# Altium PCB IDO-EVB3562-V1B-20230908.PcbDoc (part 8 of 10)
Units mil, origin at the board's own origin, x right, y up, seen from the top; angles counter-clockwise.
Board outline 5314.96 x 3543.31 mil, 4 copper layers (TOP, L2-VCC, L3-GND, BOTTOM), stack 28.8 mil thick; 747 components, 560 nets, 2514 pads, 1964 vias.
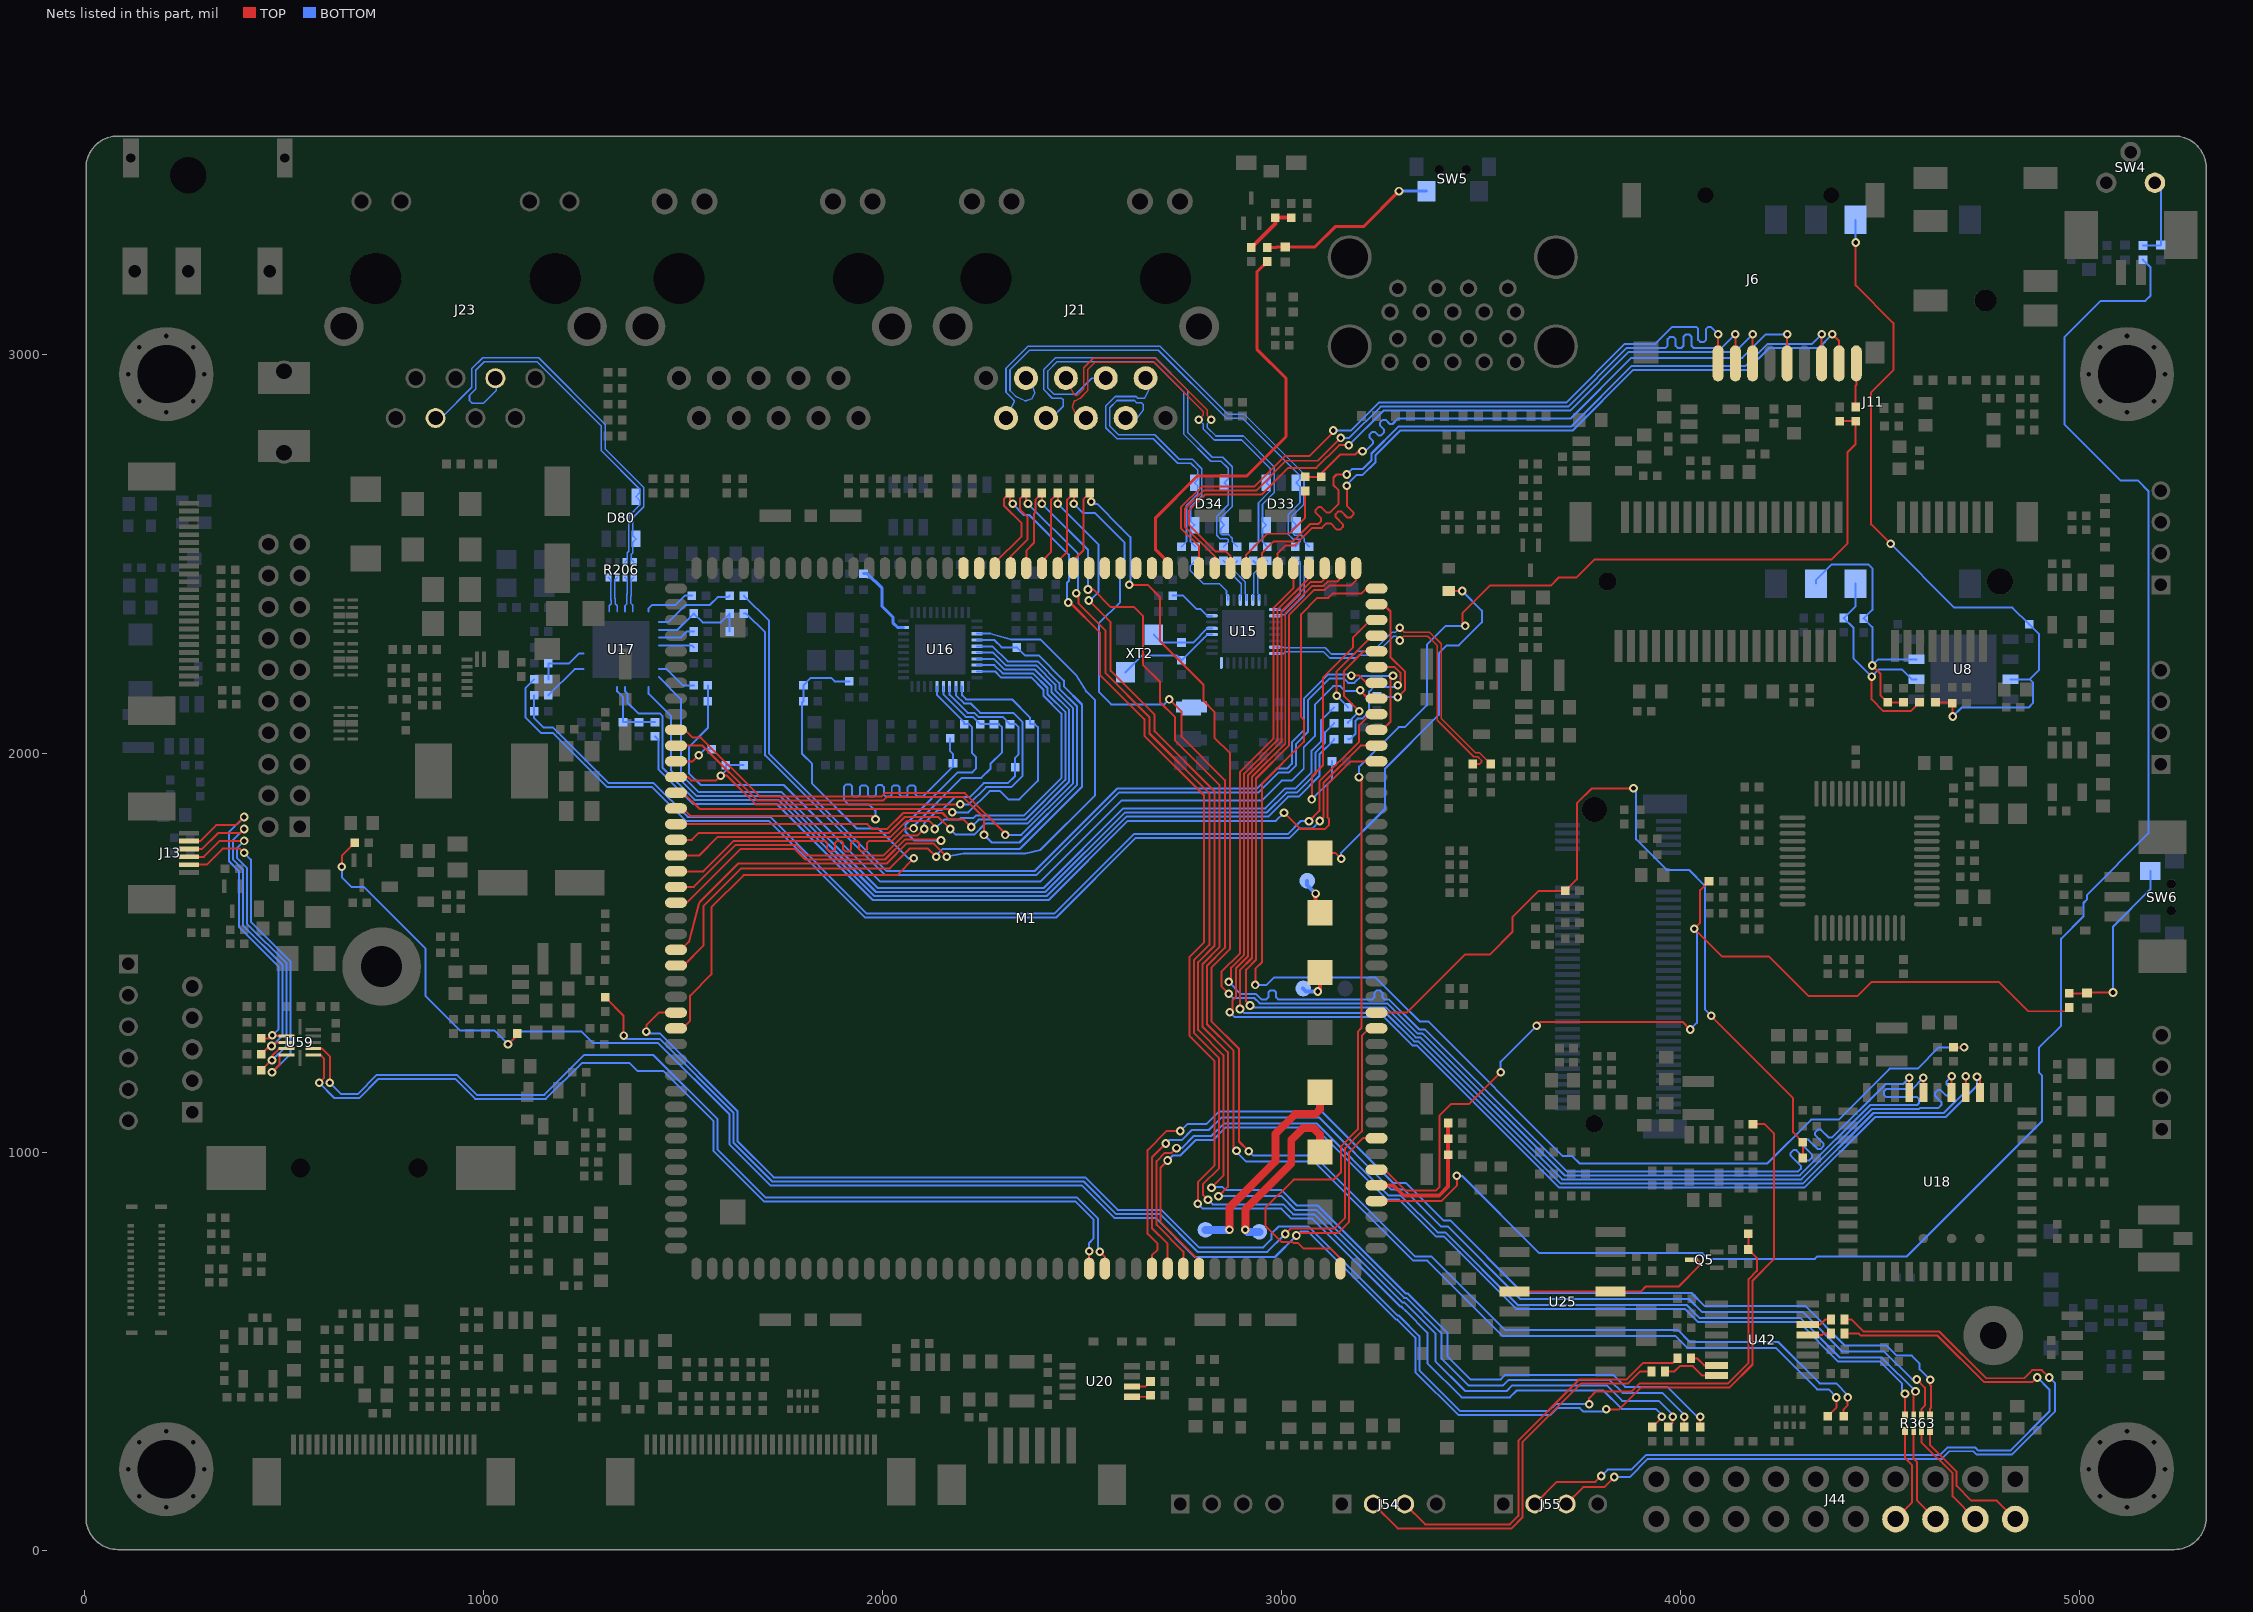
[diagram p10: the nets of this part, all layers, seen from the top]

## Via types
v1: diameter 21.65, hole 11.81, TOP to BOTTOM, 1964 vias

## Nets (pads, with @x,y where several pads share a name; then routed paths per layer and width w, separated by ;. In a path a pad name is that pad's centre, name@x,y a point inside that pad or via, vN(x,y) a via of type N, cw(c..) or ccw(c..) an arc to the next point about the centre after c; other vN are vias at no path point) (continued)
PHY2_MDI0-: R144.1 U15.2 | length 166.1
  BOTTOM w4: R144.1@2785,2482.28 2772,2469.28 2772,2458.14 2805.14,2425 2845,2425 2862.76,2407.24 2862.76,2398.24 2865.63,2395.37 U15.2@2865.63,2383.74
PHY2_MDI1+: R149.1 U15.4 | length 118.4
  BOTTOM w4: R149.1@2855,2482.28 2867.5,2469.78 2867.5,2457.5 2900,2425 2900,2399 2897.13,2396.13 U15.4@2897.13,2383.74
PHY2_MDI1-: R148.1 U15.5 | length 118.4
  BOTTOM w4: R148.1@2890,2482.28 2877.5,2469.78 2877.5,2461.64 2910,2429.14 2910,2399 2912.87,2396.13 U15.5@2912.87,2383.74
PHY2_MDI2+: R142.1 U15.6 | length 109.5
  BOTTOM w4: U15.6@2928.62,2383.74 2928.62,2396.62 2931.49,2399.49 2931.49,2450.64 2942.5,2461.64 2942.5,2469.78 R142.1@2930,2482.28
PHY2_MDI2-: R141.1 U15.7 | length 109.5
  BOTTOM w4: U15.7@2944.37,2383.74 2944.37,2396.63 2941.49,2399.51 2941.49,2446.49 2952.5,2457.5 2952.5,2469.78 R141.1@2965,2482.28
PHY2_MDI3+: R147.1 U15.9 | length 175.4
  BOTTOM w4: U15.9@2983.74,2360.12 2997.88,2360.12 3000.76,2357.24 3005.1,2357.24 3047.5,2399.64 3047.5,2478.5 3043.72,2482.28 R147.1@3035,2482.28
PHY2_MDI3-: R140.1 U15.10 | length 186.9
  BOTTOM w4: U15.10@2983.74,2344.37 2997.37,2344.37 3000.24,2347.24 3009.24,2347.24 3057.5,2395.5 3057.5,2469.78 R140.1@3070,2482.28
PHY2_MDI_0+: D34.4 J21.2 R145.2 | length 707.7
  BOTTOM w4: J21.2@2660,2940 2669,2913 2657.5,2890 2640.2,2890 2636.2,2894 2584,2894 2560,2870 2560,2816 2588,2788 2679,2788 2740.36,2726.64 2773.22,2726.64 2791,2708.86 2791,2686.55 D34.4@2782.6,2678.15 2791,2669.75 2791,2650.14 2762.5,2621.64 2762.5,2530.22 R145.2@2750,2517.72
PHY2_MDI_0-: D34.3 J21.3 R144.2 | length 707.7
  BOTTOM w4: J21.3@2610,2840 2621.6,2834.2 2639.31,2840.1 2654,2860.49 2654,2874.03 2650,2878.03 2638.03,2878.03 2632.05,2884 2588.14,2884 2570,2865.86 2570,2820.14 2592.14,2798 2683.14,2798 2744.51,2736.64 2777.36,2736.64 2801,2713 2801,2646 2772.5,2617.5 2772.5,2581.95 D34.3@2782.6,2571.85 2772.5,2561.75 2772.5,2530.22 R144.2@2785,2517.72
PHY2_MDI_1+: D34.6 J21.4 R149.2 | length 1088.6
  BOTTOM w4: J21.4@2560,2940 2525,2940 2485,2900 2430,2900 2415,2915 2415,2958 2438,2981 2679.86,2981 2756,2904.86 2756,2799 2823,2732 2848.86,2732 2867,2713.86 2867,2687.75 D34.6@2857.4,2678.15 2867,2668.55 2867,2622.41 2838,2593.41 2838,2546 2847,2537 2864.86,2537 2867.07,2534.79 2867.07,2529.79 R149.2@2855,2517.72
PHY2_MDI_1-: D34.1 J21.7 R148.2 | length 1088.8
  BOTTOM w4: J21.7@2410,2840 2424,2840 2453.29,2869.29 2453.29,2885.71 2449,2890 2425.86,2890 2405,2910.86 2405,2962.14 2433.86,2991 2684,2991 2766,2909 2766,2803.14 2827.14,2742 2853,2742 2877,2718 2877,2618.27 2848,2589.27 2848,2581.25 D34.1@2857.4,2571.85 2848,2562.45 2848,2550.14 2851.14,2547 2869,2547 2877.07,2538.93 2877.07,2530.65 R148.2@2890,2517.72
PHY2_MDI_2+: D33.4 J21.5 R142.2 | length 989.8
  TOP w4: J21.5@2510,2840 2486,2848 2476.4,2867.2 2481.57,2882.69 2495.84,2889.83 2515,2908.99 2515,2961.86 2533.14,2980 2680.86,2980 2804,2856.86 2804,2846.83 v1(2793.17,2836)
  BOTTOM w4: v1(2793.17,2836) 2804,2825.17 2804,2813 2832,2785 2901,2785 2972,2714 2972,2687.55 D33.4@2962.6,2678.15 2972,2668.75 2972,2657 2943,2628 2943,2530.72 R142.2@2930,2517.72
PHY2_MDI_2-: D33.3 J21.6 R141.2 | length 990.3
  TOP w4: J21.6@2460,2940 2480.98,2898.05 2486.34,2896.26 2489.92,2898.05 2505,2913.13 2505,2966 2529,2990 2685,2990 2814,2861 2814,2846.83 v1(2824.83,2836)
  BOTTOM w4: v1(2824.83,2836) 2814,2825.17 2814,2817.14 2836.14,2795 2905.14,2795 2982,2718.14 2982,2652.86 2953,2623.86 2953,2581.45 D33.3@2962.6,2571.85 2953,2562.25 2953,2529.72 R141.2@2965,2517.72
PHY2_MDI_3+: D33.6 J21.8 R147.2 | length 1281.2
  BOTTOM w4: J21.8@2360,2940 2372,2934 2382.2,2903.4 2374.6,2888.2 2358.4,2882.8 2333.71,2895.15 2320,2908.86 2320,2960.86 2369.14,3010 2691.87,3010 2861.87,2840 2902.38,2840 3047,2695.38 3047,2687.75 D33.6@3037.4,2678.15 3037.4,2677.6 3047,2668 3047,2628 3018,2599 3018,2547.86 3029.86,2536 3045.86,2536 3048,2533.86 3048,2530.72 R147.2@3035,2517.72
PHY2_MDI_3-: D33.1 J21.9 R140.2 | length 1269.3
  BOTTOM w4: J21.9@2310,2840 2330.98,2881.95 2330.02,2884.81 2329.78,2884.93 2310,2904.72 2310,2965 2365,3020 2696.01,3020 2866.01,2850 2906.52,2850 3057,2699.52 3057,2623.86 3028,2594.86 3028,2581.25 D33.1@3037.4,2571.85 3028,2562.45 3028,2552 3034,2546 3050,2546 3058,2538 3058,2529.72 R140.2@3070,2517.72
PHY2_REG_OUT: L32.1 R1064.1 U15.24
PHY2_XTALIN: C116.1 U15.28 XT2.3 | length 266
  BOTTOM w5: XT2.3@2609.57,2202.76 2651.81,2245 2737.72,2245 C116.1@2750,2232.72 2814.41,2297.13 U15.28@2826.26,2297.13
PHY2_XTALOUT: C115.1 U15.29 XT2.1 | length 168.8
  BOTTOM w5: XT2.1@2680.43,2297.24 2700.4,2277.28 C115.1@2750,2277.28 2779.15,2277.28 2814.74,2312.87 U15.29@2826.26,2312.87
PHY_INT: R195.1 U17.11 | length 94.2
  BOTTOM w5: U17.11@1439.5,2289.55 1494.55,2289.55 1510,2305 R195.1@1527.28,2305
PMIC_32KOUT_WIFI: M1.16 R243.1 R342.1 R391.1 | length 2146.4
  TOP w5: M1.16@3238.78,1349.61 3314.61,1349.61 3460,1495 3522.54,1495 3579.14,1551.6 3579.14,1589.17 3644.97,1655 R342.1@3712.28,1655 3741.08,1683.8 3741.08,1874.18 3778.91,1912 v1(3883,1912) ; v1(4077.7,1341.57) 4077.7,1340.38 4283,1135.08 4283,1049.28 R243.1@4307.28,1025 R391.1@4307.28,985
  BOTTOM w5: v1(3883,1912) 3889.5,1905.5 3889.5,1783.95 3965.95,1707.5 4022.17,1707.5 4061.67,1668 4061.67,1357.6 v1(4077.7,1341.57)
PMIC_EXT_EN: M1.8 R4.1 R9.1 R1171.1 | length 5602.8
  TOP w5: v1(645,1715) 645,1742.72 R4.1@677.28,1775 ; v1(1061.65,1270) 1085,1293.35 R9.1@1085,1297.28 ; v1(3038,790.67) 3044.33,797 3142,797 3170,825 3170,1000 3204.65,1034.65 M1.8@3238.78,1034.65 ; v1(3814.48,355) 3847.18,355 3902.48,410.3 4124.21,410.3 4181.35,467.44 4181.35,677.18 4235,730.83 4235,1046.67 4211.67,1070 R1171.1@4182.72,1070
  BOTTOM w5: v1(645,1715) 645,1689.08 669.08,1665 700,1665 855,1510 855,1391 941,1305 1026.65,1305 v1(1061.65,1270) 1093.65,1302 1246,1302 1274.33,1273.67 1437.42,1273.67 1616.91,1094.18 1616.91,1018.66 1719.25,916.33 2500.1,916.33 2581.43,835 2685,835 2783,737 2984.33,737 v1(3038,790.67) 3048.33,801 3066.71,801 3287.71,580 3291,580 3336.33,534.67 3336.33,448.53 3444.53,340.33 3673.94,340.33 3691.94,358.33 3748.67,358.33 3757.35,349.65 3809.12,349.65 v1(3814.48,355)
PMIC_PWRON: M1.4 R267.1 | length 4490.3
  TOP w5: M1.4@3238.78,877.16 3401.16,877.16 3440,916 v1(3440,940.5)
  BOTTOM w5: v1(3440,940.5) 3453.11,940.5 3646.94,746.67 4055.63,746.67 4070.09,732.21 4337.45,732.21 4343.46,738.22 4568.22,738.22 4906.67,1076.67 4906.67,1192.33 4899.35,1199.65 4899.35,1260.99 4955,1316.64 4955,1535 5011,1591 5011,1624.43 5020,1633.43 5020,1645 5173.88,1798.88 5173.88,2657.12 5147,2684 5103.22,2684 4963.5,2823.72 4963.5,3043.5 5054,3134 5166,3134 5179,3147 5179,3218.28 R267.1@5160,3237.28
PMIC_SLEEP_H: M1.15 R1083.1 | length 2746.1
  TOP w5: R1083.1@1305,1387.72 1351.6,1341.12 v1(1351.6,1292) ; v1(3010,794.67) 3024.33,809 3134,809 3160,835 3160,1010 3202,1052 3202,1292 3220.24,1310.24 M1.15@3238.78,1310.24
  BOTTOM w5: v1(1351.6,1292) 1359.92,1283.67 1441.56,1283.67 1626.91,1098.33 1626.91,1022.81 1723.39,926.33 2504.25,926.33 2585.57,845 2695,845 2790,750 2965.33,750 v1(3010,794.67)
PMIC_VDC: C302.2 M1.5 R17.1 R389.2 | length 359
  TOP w10: M1.5@3238.78,916.53 3281.47,916.53 3307,891 3396,891 3418.28,913.28 R17.1@3418.28,993 C302.2@3418.28,1033 R389.2@3418.28,1073
PWRON_KEY: D51.1 R267.2 SW4.1 | length 207.8
  BOTTOM w5: R267.2@5160,3272.72 5203.82,3272.72 D51.1@5205,3273.9 5205,3415 SW4.1@5190,3430
RECOVERY_KEY: D46.1 R264.2 SW5.4 | length 457.6
  TOP w8: R264.2@2965,3267.72 2987.72,3267.72 2988.9,3268.9 D46.1@3010,3268.9 3083.9,3268.9 3135,3320 3206.02,3320 v1(3295,3408.98)
  BOTTOM w8: v1(3295,3408.98) SW5.4@3364.05,3408.98
REFCLKN_100M_RJ45: R404.2 U15.16 | length 826.9
  TOP w4: v1(3297.17,2282.53) 3297.17,2284.01 3306.51,2293.36 3367.5,2293.36 3390.75,2270.11 3390.75,2082.8 3482.55,1991 3492.58,1991 3502,1981.58 3502,1977 3497.72,1972.72 R404.2@3480,1972.72
  BOTTOM w4: U15.16@2983.74,2249.88 3005.7,2249.88 3009.81,2254 3105.86,2254 3121.25,2238.6 3187.6,2238.6 3194,2245 3233.14,2245 3281.5,2293.36 3287.82,2293.36 3297.17,2284.01 v1(3297.17,2282.53)
REFCLKP_100M_RJ45: R403.2 U15.15 | length 826.6
  TOP w4: v1(3297.17,2314.18) 3307.99,2303.36 3371.64,2303.36 3400.75,2274.25 3400.75,2086.95 3486.7,2001 3496.72,2001 R403.2@3525,1972.72
  BOTTOM w4: U15.15@2983.74,2265.63 3005.7,2265.63 3007.32,2264 3110,2264 3125.4,2248.6 3183.46,2248.6 3189.86,2255 3229,2255 3277.36,2303.36 3286.34,2303.36 v1(3297.17,2314.18)
RESET_KEY: D50.1 R266.2 SW6.4 | length 454.1
  TOP w5: R266.2@4975,1397.72 5018.82,1397.72 D50.1@5020,1398.9 5021.1,1400 v1(5085,1400)
  BOTTOM w5: v1(5085,1400) 5085,1565 5178.48,1658.48 SW6.4@5178.48,1704.44
RESETN: M1.6 R36.1 R266.1 | length 2567.6
  TOP w5: M1.6@3238.78,955.91 3259.77,955.91 3312.18,903.5 3387.5,903.5 3397,913 3397,1092 3425,1120 3470,1120 v1(3550,1200) ; v1(3640,1316.67) 3649.33,1326 4006.08,1326 v1(4025,1307.08) ; R36.1@4072.28,1679 4050,1656.72 4050,1575 v1(4035,1560) 4105,1490 4223,1490 4322,1391 4444,1391 4479.93,1426.93 4798.07,1426.93 4872,1353 4965.72,1353 R266.1@4975,1362.28
  BOTTOM w5: v1(3550,1200) 3550,1226.67 v1(3640,1316.67) ; v1(4025,1307.08) 4041.67,1323.75 4041.67,1553.33 v1(4035,1560)
RGMII_CLK_M0: C130.2 M1.115 R170.1 R171.2 | length 1624.6
  TOP w5: M1.115@1482.87,1310.24 1499.24,1310.24 1517.93,1328.93 1517.93,1391.93 1571.29,1445.29 1571.29,1613.49 1652.15,1694.35 2036.86,1694.35 v1(2078.76,1736.25)
  BOTTOM w5: R170.1@1917.28,2180 1880.51,2180 1871.84,2188.66 1820.94,2188.66 R171.2@1802.28,2170 C130.2@1802.28,2130.01 1799.07,2126.81 1799.07,1997.87 1823.92,1973.02 1823.92,1923.52 1936.26,1811.18 1990.06,1811.18 2064.99,1736.25 v1(2078.76,1736.25)
RGMII_MDC_M0: M1.110 U16.13 | length 1871.8
  TOP w5: M1.110@1482.87,1507.09 1495.09,1507.09 1515.19,1527.19 1540.34,1623.2 1543.45,1628.08 1638.72,1723.35 2010.73,1723.35 2060.36,1772.98 2129.13,1772.98 v1(2161.65,1740.46)
  BOTTOM w5: v1(2161.65,1740.46) 2203.62,1748 2358.74,1748 2396.01,1757.17 2532.5,1893.66 2532.5,2133.46 2510.98,2154.98 2485.97,2195.32 2396.22,2285.07 2323.07,2285.07 2271,2299.37 U16.13@2237.52,2299.37
RGMII_MDIO_M0: M1.111 R191.1 U16.14 | length 1825.8
  TOP w5: M1.111@1482.87,1467.72 1501.72,1467.72 1552,1518 1552,1617 1646,1711 2019,1711 2069,1761 2114,1761 v1(2135,1740)
  BOTTOM w5: v1(2135,1740) 2135,1744 2151,1760 2345,1760 2500.5,1915.5 2500.5,2122.03 2454.97,2167.56 2454.97,2182.03 2392,2245 2357.28,2245 R191.1@2337.28,2265 2299,2265 2280.38,2283.62 U16.14@2237.52,2283.62
RGMII_RXCLK_M0: C143.2 M1.101 R192.2 | length 1238.4
  TOP w5: M1.101@1482.87,1861.42 1499.58,1861.42 1518.17,1842.83 1974.5,1842.83 v1(1982.83,1834.5)
  BOTTOM w5: v1(1982.83,1834.5) 1982.83,1855.17 1966.84,1871.16 1915.84,1871.16 1903.56,1883.44 1903.56,1915.67 1909.56,1921.67 1919.56,1921.67 1923.56,1917.67 1923.56,1896.16 1928.56,1891.16 1938.56,1891.16 1943.56,1896.16 1943.56,1914 1948.56,1919 1958.56,1919 1963.56,1914 1963.56,1896.16 1968.56,1891.16 1978.56,1891.16 1983.56,1896.16 1983.56,1914.76 1988.56,1919.76 1998.56,1919.76 2003.56,1914.76 2003.56,1896.16 2008.56,1891.16 2018.56,1891.16 2023.56,1896.16 2023.56,1914 2028.56,1919 2038.56,1919 2043.56,1914 2043.56,1896.16 2048.56,1891.16 2058.56,1891.16 2063.56,1896.16 2063.56,1914 2068.56,1919 2078.56,1919 2083.56,1914 2083.56,1896.16 2088.56,1891.16 2101.16,1891.16 2177.28,1967.28 C143.2@2177.28,1975.01 2177.28,1997.72 2170,2005 R192.2@2170,2037.28
RGMII_RXD0_M0: M1.105 R181.2 R182.1 U16.25 | length 1336.5
  TOP w5: M1.105@1482.87,1703.94 1551.43,1703.94 1627.49,1780 1856.86,1780 1861.86,1775 1861.86,1759 1866.86,1754 1876.86,1754 1881.86,1759 1881.86,1775 1886.86,1780 1896.86,1780 1901.86,1775 1901.86,1759 1906.86,1754 1916.86,1754 1921.86,1759 1921.86,1775 1926.86,1780 1936.86,1780 1941.86,1775 1941.86,1759 1946.86,1754 1956.86,1754 1961.86,1759 1961.86,1775 1966.86,1780 2024.95,1780 2056.26,1811.3 v1(2078.33,1811.3)
  BOTTOM w5: v1(2078.33,1811.3) 2078.33,1817.33 2199,1938 2248,1938 2271.11,1961.11 2271.11,1973.17 2300,2002.07 2300,2065 2292.28,2072.72 R182.1@2280,2072.72 R181.2@2245,2072.72 2226.65,2091.07 2208.93,2091.07 2152.87,2147.13 U16.25@2152.87,2167.48
RGMII_RXD1_M0: M1.106 R184.2 R185.1 U16.24 | length 1349.3
  TOP w5: M1.106@1482.87,1664.57 1527.57,1664.57 1633,1770 1783.95,1770 1810.61,1743.35 2002.44,1743.35 2052.07,1792.98 2087.98,1792.98 v1(2105,1810)
  BOTTOM w5: v1(2105,1810) 2105,1823.83 2138.17,1857 2149,1857 2182,1890 2219,1890 2253.72,1924.72 2314.72,1924.72 2332.72,1942.72 R185.1@2332.72,1965 2332.72,1988.35 2341.65,1997.28 2341.65,2065.35 2334.28,2072.72 R184.2@2320,2072.72 2301.65,2091.07 2240.79,2091.07 2230.79,2101.07 2213.93,2101.07 2168.62,2146.38 U16.24@2168.62,2167.48
RGMII_RXD2_M0: M1.99 R187.2 R188.1 U16.23 | length 1363.9
  TOP w5: M1.99@1482.87,1940.16 1512.46,1940.16 1520.62,1932 1583.57,1932 v1(1595,1943.43) 1610.49,1943.43 1682.25,1871.67 v1(2195,1871.67)
  BOTTOM w5: v1(1595,1943.43) 1607.72,1956.15 R187.2@1607.72,1970 R188.1@1652.28,1970 ; U16.23@2184.37,2167.48 2184.37,2145.63 2205,2125 2221.01,2125 2244.93,2101.07 2327.93,2101.07 2351.65,2077.35 2351.65,1943.77 2322.6,1914.72 2260.01,1914.72 2216.96,1871.67 v1(2195,1871.67)
RGMII_RXD3_M0: M1.100 R178.1 U16.22 | length 1367.6
  TOP w5: M1.100@1482.87,1900.79 1501.21,1900.79 1542,1860 2166.67,1860 v1(2175,1851.67)
  BOTTOM w5: v1(2175,1851.67) 2215.67,1851.67 2268.72,1904.72 2295.28,1904.72 2316,1884 2343.72,1884 2390,1930.28 2390,2065 2382.28,2072.72 R178.1@2370,2072.72 2370,2090 2325,2135 2210,2135 2200.12,2144.88 U16.22@2200.12,2167.48
RGMII_RXDV_M0: M1.107 R180.2 U16.26 | length 1357
  TOP w5: M1.107@1482.87,1625.2 1510.2,1625.2 1645,1760 1779.81,1760 1806.46,1733.35 2006.58,1733.35 2056.21,1782.98 2145.05,1782.98 v1(2147.02,1781.01)
  BOTTOM w5: U16.26@2137.13,2167.48 2137.13,2145.59 2205,2077.72 R180.2@2205,2072.72 2217.28,2072.72 2225,2065 2225,2000 2234.54,1990.46 2234.54,1961.05 2225.49,1952 2189,1952 2058,1821 2058,1803 2079.99,1781.01 v1(2147.02,1781.01)
RGMII_TXCLK_M0: M1.98 R177.1 | length 102
  TOP w5: M1.98@1482.87,1979.53 1524.53,1979.53 v1(1540,1995)
  BOTTOM w5: v1(1540,1995) 1555,2010 R177.1@1572.28,2010
RGMII_TXD0_M0: M1.102 U16.18 | length 1509.6
  TOP w5: M1.102@1482.87,1822.05 1962.3,1822.05 1974.35,1810 2012.52,1810 2052.52,1850 2150.75,1850 2167.41,1833.35 2204.43,1833.35 v1(2222.89,1814.88)
  BOTTOM w5: v1(2222.89,1814.88) 2241.38,1833.37 2358.8,1833.37 2458.5,1933.07 2458.5,2103.46 2413.97,2147.99 2413.97,2163.32 2377.29,2200 2301.43,2200 2280.8,2220.63 U16.18@2237.52,2220.63
RGMII_TXD1_M0: M1.103 U16.17 | length 1554.7
  TOP w5: M1.103@1482.87,1782.68 1522.68,1782.68 1540,1800 2016.66,1800 2056.66,1840 2140,1840 v1(2170,1810)
  BOTTOM w5: v1(2170,1810) 2184.08,1795.92 2229.85,1795.92 2257.3,1823.37 2362.94,1823.37 2468.5,1928.93 2468.5,2108.6 2423.97,2153.13 2423.97,2167.46 2381.43,2210 2305.57,2210 2279.19,2236.38 U16.17@2237.52,2236.38
RGMII_TXD2_M0: M1.96 U16.16 | length 1662.4
  TOP w5: M1.96@1482.87,2058.27 1504.73,2058.27 1524.2,2038.8 1545.2,2038.8 1692.17,1891.83 1998.29,1891.83 2006.46,1900 2206.74,1900 2308.16,1798.58 v1(2308.16,1795)
  BOTTOM w5: U16.16@2237.52,2252.13 2277.59,2252.13 2309.72,2220 2385.57,2220 2433.97,2171.61 2433.97,2157.28 2478.5,2112.74 2478.5,1924.79 2348.71,1795 v1(2308.16,1795)
RGMII_TXD3_M0: M1.97 U16.15 | length 1716.1
  TOP w5: M1.97@1482.87,2018.9 1549.17,2018.9 1686.24,1881.83 2002.43,1881.83 2010.6,1890 2202.59,1890 2254.85,1837.75 v1(2254.85,1795)
  BOTTOM w5: U16.15@2237.52,2267.87 2275.99,2267.87 2313.86,2230 2389.72,2230 2443.97,2175.75 2443.97,2161.42 2488.5,2116.89 2488.5,1920.64 2343.86,1776 2273.85,1776 v1(2254.85,1795)
RGMII_TXEN_M0: M1.104 U16.19 | length 1492
  TOP w5: M1.104@1482.87,1743.31 1540.31,1743.31 1587,1790 2020.81,1790 2060.81,1830 2118,1830 2131.65,1816.35 v1(2131.65,1810)
  BOTTOM w5: v1(2131.65,1810) 2155,1833.35 2191.35,1833.35 2196,1838 2229,1838 2234.37,1843.37 2354.66,1843.37 2448.5,1937.21 2448.5,2099.31 2403.97,2143.85 2403.97,2159.18 2373.14,2190 2297.28,2190 2282.4,2204.88 U16.19@2237.52,2204.88
RMII_CLK: C155.2 M1.36 R213.1 | length 2372.5
  TOP w5: v1(3198.05,2158.01) 3198.05,2156.44 3217.48,2137.01 M1.36@3238.78,2137.01
  BOTTOM w5: R213.1@1562.72,2170 C155.2@1562.72,2129.99 1562.72,2063 1515,2015.28 1515,1950 1544.89,1920.11 1752.38,1920.11 1994.56,1677.92 2395.92,1677.92 2599.8,1881.8 2951.78,1881.8 3000.91,1930.93 3026.77,1930.93 3056.35,1960.51 3056.35,2014.5 3085,2043.15 3085,2122.57 3130.18,2167.75 3147.96,2167.75 3159.61,2156.1 3196.14,2156.1 v1(3198.05,2158.01)
RMII_CLK_: R213.2 U17.15 | length 104.7
  BOTTOM w5: U17.15@1439.5,2210.75 1459.25,2210.75 1500,2170 R213.2@1527.28,2170
RMII_CLK_CTL: R216.1 U17.12 | length 89.8
  BOTTOM w5: U17.12@1439.5,2269.85 1522.43,2269.85 R216.1@1527.28,2265
RMII_CRS_DV: M1.35 R215.1 R1198.2 | length 2646.1
  TOP w5: v1(3069.55,1829.33) 3095.29,1855.07 3095.29,1929.37 3195,2029.08 3195,2070 3222.64,2097.64 M1.35@3238.78,2097.64
  BOTTOM w5: R215.1@1127.28,2145 R1198.2@1127.28,2105 1127.28,2087.72 1150.16,2064.84 1174.27,2064.84 1314.1,1925.02 1426.84,1925.02 1511.75,1840.11 1719.23,1840.11 1961.41,1597.92 2431.18,1597.92 2630.3,1797.04 3015.87,1797.04 3048.16,1829.33 v1(3069.55,1829.33)
RMII_CRS_DVALID: R215.2 U17.26 | length 115
  BOTTOM w5: R215.2@1162.72,2145 1228.47,2210.75 U17.26@1250.5,2210.75
RMII_MDC: M1.42 R203.1 | length 332.8
  TOP w5: M1.42@3238.78,2373.23 3255.77,2373.23 3273.84,2355.16 3273.84,2240.22 3310.49,2203.57 3310.49,2158.99 v1(3292.17,2140.66)
  BOTTOM w5: R203.1@3240,2142.72 3263.35,2142.72 3265.41,2140.66 v1(3292.17,2140.66)
RMII_MDIO: M1.41 R202.1 | length 642.9
  TOP w5: v1(3076.46,1883.99) 3076.46,1941.46 3104,1969 3104,2189.14 3180,2265.14 3180,2290 3223.86,2333.86 M1.41@3238.78,2333.86
  BOTTOM w5: v1(3076.46,1883.99) 3127.28,1934.81 R202.1@3127.28,1980
RMII_RST_: C340.2 R204.1 R208.2 U17.21 | length 173.9
  BOTTOM w5: U17.21@1335.15,2165.5 1335.15,2154.85 1350,2140 C340.2@1350,2077.72 R204.1@1390,2077.72 R208.2@1430,2077.72
RMII_RSTN: M1.32 R208.1 | length 2265.4
  TOP w5: v1(3006.97,1850.37) 3047.34,1810 3110,1810 3120,1820 3120,1835 3115.29,1839.71 3115.29,1921.09 3173.73,1979.53 M1.32@3238.78,1979.53
  BOTTOM w5: R208.1@1430,2042.28 1438.35,2033.93 1438.35,1959.93 1525.18,1873.11 1734.66,1873.11 1975.84,1631.92 2416.75,1631.92 2614.87,1830.04 2986.64,1830.04 v1(3006.97,1850.37)
RMII_RXD0: M1.37 R197.2 | length 2358
  TOP w5: v1(3175.72,2194.42) 3195.58,2194.42 3213.62,2176.38 M1.37@3238.78,2176.38
  BOTTOM w5: R197.2@1652.72,2395 1716.07,2331.65 1716.07,1998.84 2009.99,1704.92 2382.61,1704.92 2589.49,1911.8 2939.36,1911.8 2988.49,1960.93 3014.34,1960.93 3026.35,1972.94 3026.35,2026.93 3056.64,2057.22 3056.64,2136.64 3117.75,2197.75 3172.4,2197.75 v1(3175.72,2194.42)
RMII_RXD1: M1.34 R196.2 | length 2535
  TOP w5: M1.34@3238.78,2058.27 3253.27,2058.27 3273.84,2078.84 3273.84,2187.84 v1(3280,2194)
  BOTTOM w5: R196.2@1652.72,2350 1659,2350 1706.07,2302.93 1706.07,1994.7 2005.84,1694.92 2386.76,1694.92 2593.63,1901.8 2943.5,1901.8 2992.63,1950.93 3018.49,1950.93 3036.35,1968.79 3036.35,2022.79 3066.64,2053.07 3066.64,2132.49 3121.89,2187.75 3156.24,2187.75 3167.9,2176.1 3183.32,2176.1 3201.22,2194 v1(3280,2194)
RMII_RXER: M1.33 R210.1 | length 2674.9
  TOP w5: v1(3096.2,1830) 3105.29,1839.1 3105.29,1925.23 3198.96,2018.9 M1.33@3238.78,2018.9
  BOTTOM w5: R210.1@1127.28,2185 1105,2162.72 1105,2090 1145,2050 1174.97,2050 1309.95,1915.02 1422.69,1915.02 1507.61,1830.11 1715.09,1830.11 1957.27,1587.92 2435.33,1587.92 2634.44,1787.04 3020.01,1787.04 3043.97,1811 3077.2,1811 v1(3096.2,1830)
RMII_TXD0: M1.40 R199.1 | length 238.7
  TOP w5: v1(3139.07,2143.65) 3139.07,2205.07 3228.49,2294.49 M1.40@3238.78,2294.49
  BOTTOM w5: v1(3139.07,2143.65) R199.1@3167.72,2115
RMII_TXD0_: R199.2 U17.16 | length 2272.7
  BOTTOM w5: U17.16@1439.5,2191.05 1495,2135.55 1495,1947 1538.89,1903.11 1747.09,1903.11 1988.27,1661.92 2404.32,1661.92 2604.2,1861.8 2960.07,1861.8 3009.2,1910.93 3035.06,1910.93 3076.35,1952.22 3076.35,2006.22 3100,2029.87 3100,2082.72 R199.2@3132.28,2115
RMII_TXD1: M1.39 R198.1 | length 260
  TOP w5: v1(3195.16,2104.96) 3157.4,2142.72 3157.4,2206.39 3206.12,2255.12 M1.39@3238.78,2255.12
  BOTTOM w5: R198.1@3167.72,2075 3167.72,2077.52 v1(3195.16,2104.96)
RMII_TXD1_: R198.2 U17.17 | length 2243.3
  BOTTOM w5: U17.17@1413.95,2165.5 1413.95,2148.74 1470.44,2092.24 1470.44,1956.13 1533.46,1893.11 1742.95,1893.11 1984.13,1651.92 2408.47,1651.92 2608.34,1851.8 2964.21,1851.8 3013.34,1900.93 3039.2,1900.93 3086.35,1948.08 3086.35,2002.08 3110,2025.72 3110,2052.72 R198.2@3132.28,2075
RMII_TXEN: M1.38 R201.1 | length 328.4
  TOP w5: M1.38@3238.78,2215.75 3284.17,2215.75 3298.33,2201.59 3298.33,2176.16 v1(3292.17,2170)
  BOTTOM w5: R201.1@3167.72,2035 3172.72,2035 3186.07,2048.35 3186.07,2081.07 3191.63,2086.63 3202.75,2086.63 3220.3,2104.18 3220.3,2154.3 3232.1,2166.1 3288.26,2166.1 v1(3292.17,2170)
RMII_TXEN_: R201.2 U17.20 | length 2284.3
  BOTTOM w5: U17.20@1354.85,2165.5 1354.85,2155.09 1361,2148.94 1361,2127 1389,2099 1443,2099 1448.35,2093.65 1448.35,1964.08 1529.32,1883.11 1738.81,1883.11 1979.99,1641.92 2412.61,1641.92 2612.49,1841.8 2968.36,1841.8 3017.49,1890.93 3043.34,1890.93 3096.35,1943.94 3096.35,1997.93 3132.28,2033.86 R201.2@3132.28,2035
RN: R206.1 U17.6 | length 90.6
  BOTTOM w4: U17.6@1374.55,2354.5 1374.55,2370.45 1369.7,2375.3 1369.7,2394.7 1370.67,2395.67 1370.67,2434.49 R206.1@1376.5,2440.32
RP: R206.2 U17.5 | length 90.6
  BOTTOM w4: U17.5@1354.85,2354.5 1354.85,2369.85 1359.7,2374.7 1359.7,2398.84 1360.67,2399.81 1360.67,2434.49 R206.2@1354.84,2440.32
RS232_RX6: L42.1 U42.13 | length 59.6
  TOP w5: U42.13@4319.7,541.94 4355.94,541.94 4359,545 L42.1@4378.07,545
RS232_RX6_: J55.2 L42.2 | length 2029.7
  TOP w5: J55.2@3635.63,117.72 3690.91,173 3787.3,173 v1(3802.13,187.83) ; L42.2@4411.93,545 4448,545 4453,540 4645,540 4762,423 4883,423 v1(4895,435)
  BOTTOM w5: v1(3802.13,187.83) 3817.96,203.65 3877.43,203.65 3914.75,240.97 4651.82,240.97 4670.86,260 4739.08,260 4747.41,251.67 4827.49,251.67 4925.83,350.01 4925.83,404.17 v1(4895,435)
RS232_RX8: L41.1 U42.8 | length 144.7
  TOP w5: L41.1@3961.93,450 3985.7,450 3999,463.3 4031.71,463.3 4055.46,439.54 U42.8@4091.3,439.54
RS232_RX8_: J54.2 L41.2 | length 996.3
  TOP w5: J54.2@3230.63,117.72 3291.67,56.67 3577.32,56.67 3604.51,83.86 3604.51,272.69 3751.82,420 3869.75,420 3899.75,450 L41.2@3928.07,450
RS232_TX6: L43.1 U42.14 | length 63.5
  TOP w5: U42.14@4319.7,567.54 4350.54,567.54 4363,580 L43.1@4378.07,580
RS232_TX6_: J55.3 L43.2 | length 2009.9
  TOP w5: J55.3@3714.37,117.72 3756.65,160 3809.3,160 v1(3834.63,185.33) ; L43.2@4411.93,580 4430,580 4460,550 4650,550 4767,433 4862.08,433 4882.41,453.33 4906.67,453.33 v1(4925,435)
  BOTTOM w5: v1(3834.63,185.33) 3873.25,185.33 3918.89,230.97 4655.97,230.97 4675,250 4734.94,250 4743.27,241.67 4831.64,241.67 4940,350.04 4940,420 v1(4925,435)
RS232_TX8: L40.1 U42.7 | length 71.8
  TOP w5: L40.1@4026.93,483 4042.14,483 4060,465.14 U42.7@4091.3,465.14
RS232_TX8_: J54.3 L40.2 | length 987.9
  TOP w5: J54.3@3309.37,117.72 3360.41,66.67 3573.18,66.67 3594.51,88 3594.51,276.83 3747.68,430 3865.61,430 3907.28,471.67 3981.74,471.67 L40.2@3993.07,483
RSET0: R183.2 U16.39 | length 190.5
  BOTTOM w8: R183.2@1952.72,2450 1962.44,2450 1999.43,2413.02 1999.43,2367.7 2027,2340.13 2027,2326 2037.88,2315.12 U16.39@2052.48,2315.12
RSET2: R158.2 U15.31 | length 119.5
  BOTTOM w5: R158.2@2727.72,2395 2754.08,2395 2788.08,2361 2798.11,2361 2814.74,2344.37 U15.31@2826.26,2344.37
RXD0: R197.1 U17.9 | length 205.1
  BOTTOM w5: U17.9@1439.5,2328.95 1464.37,2328.95 1507.42,2372 1568,2372 1587,2391 1613.28,2391 R197.1@1617.28,2395
RXD1: R196.1 R211.1 R212.1 U17.10 | length 257.9
  BOTTOM w5: U17.10@1439.5,2309.25 1486.53,2309.25 R212.1@1527.28,2350 1549.28,2328 1595.28,2328 R196.1@1617.28,2350 R211.1@1617.28,2305
RXDV: R217.1 U17.8 | length 130.1
  BOTTOM w5: U17.8@1413.95,2354.5 1413.95,2362.95 1422,2371 1481,2371 1505,2395 R217.1@1522.28,2395
RXER/FXEN: R210.2 R220.1 U17.28 | length 138.2
  BOTTOM w5: R210.2@1162.72,2185 R220.1@1162.72,2225 1214.94,2225 1240.09,2250.15 U17.28@1250.5,2250.15
RXN: D80.4 J23.6 R206.8 | length 991.3
  BOTTOM w4: J23.6@880,2840 894,2840 971,2917 971,2964 998,2991 1138.4,2991 1305,2824.4 1305,2763 1402,2666 1402,2618 1374,2590 1374,2545.25 D80.4@1382.4,2536.85 1374,2528.45 1374,2501.86 1370.67,2498.53 1370.67,2485.51 R206.8@1376.5,2479.68
RXP: D80.3 J23.3 R206.7 | length 990.9
  BOTTOM w4: J23.3@1030,2940 1032,2938 1032,2909 1000,2877 972,2877 965,2884 965,2896.86 981,2912.86 981,2959.86 1002.14,2981 1134.26,2981 1295,2820.26 1295,2758.86 1392,2661.86 1392,2652.75 D80.3@1382.4,2643.15 1392,2633.55 1392,2622.14 1364,2594.14 1364,2506 1360.67,2502.67 1360.67,2485.51 R206.7@1354.84,2479.68
SARADC0_BOOT: M1.179 R1202.1 | length 948.8
  TOP w5: M1.179@3096.65,1750 3135,1750 v1(3150,1735) ; R1202.1@3420,2406.46 v1(3453.54,2406.46)
  BOTTOM w5: v1(3150,1735) 3150,1750 3260,1860 3260,1961 3395,2096 3395,2250 3415,2270 3445,2270 3503,2328 3503,2357 v1(3453.54,2406.46)
SARADC0_IN1_KEY/RECOVERY: M1.56 R264.1 | length 1030
  TOP w8: M1.56@2715.16,2463.78 2715.16,2479.84 2685,2510 2685,2590.07 2789.76,2694.83 2913.31,2694.83 3011.98,2793.49 3011.98,2939.66 2938.8,3012.84 2938.8,3206.07 R264.1@2965,3232.28
SARADC0_IN3: M1.57
SARADC0_IN4: M1.58
SARADC0_IN5: M1.59
SARADC0_IN6: M1.60
SARADC0_IN7: M1.61
SARADC1_IN0: C272.2 M1.62 R350.1 | length 3906.2
  TOP w5: M1.62@2478.94,2463.78 2478.94,2482.94 2504,2508 2504,2636.28 C272.2@2520,2652.28 2520,2636 2524,2632 v1(2524,2630) ; v1(2619.17,2421.84) 2665.16,2421.84 2696,2391 2696,2280 2805,2171 2805,2131 2832.5,2103.5 2832.5,2038.61 2871.65,1999.45 2871.65,1509.24 2824.8,1462.39 2824.8,1328.26 2894,1259.06 2894,1026.5 v1(2918.68,1001.82) ; R350.1@4410,337.72 4410,355 4420,365 v1(4420,385)
  BOTTOM w5: v1(2524,2630) 2527,2627 2529,2627 2531,2625 2538.36,2625 2598.02,2565.34 2621.68,2541.68 2621.68,2424.34 v1(2619.17,2421.84) ; v1(2918.68,1001.82) 2929.65,990.85 3082.72,990.85 3335,738.57 3376.25,738.57 3560.61,554.22 3993.51,554.22 4023.38,524.35 4245.27,524.35 4349.62,420 4391.11,420 4419.24,391.87 4419.24,385.76 v1(4420,385)
SARADC1_IN1: C273.2 M1.63 R349.1 | length 4052.7
  TOP w5: M1.63@2439.57,2463.78 2439.57,2481.57 2463.33,2505.33 2463.33,2635.61 C273.2@2480,2652.28 v1(2480,2625) ; v1(2719.32,2134.69) 2750,2104.01 2750,2041 2858.65,1932.35 2858.65,1511.8 2813.8,1466.95 2813.8,1320.88 2879.88,1254.8 2879.88,1011.09 v1(2887.88,1003.09) ; R349.1@4370,337.72 4391.59,359.31 v1(4391.59,384.63)
  BOTTOM w5: v1(2480,2625) 2503.33,2601.67 2533.4,2601.67 2606.68,2528.39 2606.68,2448 2595.85,2437.17 2595.85,2378.7 2542.5,2325.36 2542.5,2153.43 2573.66,2122.28 2706.91,2122.28 v1(2719.32,2134.69) ; v1(2887.88,1003.09) 2887.88,999.63 2911.66,975.85 3082.16,975.85 3330.44,727.57 3366.03,727.57 3554.39,539.22 3987.3,539.22 4017.16,509.35 4239.06,509.35 4343.41,405 4372.44,405 4391.59,385.86 v1(4391.59,384.63)
SARADC1_IN2: C274.2 M1.64 R348.1 | length 3721.1
  TOP w5: M1.64@2400.2,2463.78 2400.2,2481.2 2423.33,2504.33 2423.33,2635.61 C274.2@2440,2652.28 v1(2440,2625) ; v1(2517.23,2382.78) 2572,2328.01 2572,2206.42 2682.65,2095.77 2682.65,2054.68 2832.65,1904.68 2832.65,1516.91 2791.8,1476.06 2791.8,1306.11 2855,1242.91 2855,940.62 v1(2825.01,910.56) v1(2825.01,910.56) ; R348.1@4050,310.72 v1(4050,336.43)
  BOTTOM w5: v1(2440,2625) 2541.7,2523.3 2541.7,2403.53 2520.93,2382.77 v1(2517.23,2382.78) ; v1(2825.01,910.56) v1(2825.01,910.56) 2826.99,912.61 2852.34,912.61 2859.96,905 3000,905 3039,866 3091.86,866 3312.61,645.25 3317.69,645.25 3416.33,546.61 3416.33,487.88 3473.88,430.33 3550.33,430.33 3561.3,441.3 3831.88,441.3 3861.83,411.35 3968.07,411.35 4042.99,336.43 v1(4050,336.43)
SARADC1_IN3: C275.2 M1.65 R347.1 | length 3721
  TOP w5: M1.65@2360.83,2463.78 2360.83,2507.83 2380.2,2527.2 2380.2,2600.2 2383.33,2603.33 2383.33,2635.61 C275.2@2400,2652.28 v1(2400,2625) ; v1(2515.57,2410.39) 2528.61,2410.39 2573,2366 2631,2366 2653,2344 2653,2222 2695.99,2179.01 2695.99,2128.01 2734,2090 2734,2031.62 2845.65,1919.96 2845.65,1514.36 2802.8,1471.5 2802.8,1313.49 2866,1250.29 2866,912.61 v1(2842.68,889.29) ; R347.1@4010,310.72 v1(4010,336.43)
  BOTTOM w5: v1(2400,2625) 2515.57,2509.43 v1(2515.57,2410.39) ; v1(2842.68,889.29) 2843.39,890 2999.44,890 3034.44,855 3087.3,855 3308.05,634.25 3313.13,634.25 3397.33,550.05 3397.33,549.67 3401.33,545.67 3401.33,482.67 3469,415 3556,415 3569.3,428.3 3823.67,428.3 3855.62,396.35 3954.78,396.35 4010,341.13 v1(4010,336.43)
SARADC1_IN4: C276.2 M1.66 R346.1 | length 3727
  TOP w5: M1.66@2321.46,2463.78 2321.46,2493.46 2364,2536 2364,2591 2345,2610 2345,2637.28 C276.2@2360,2652.28 2360,2630.6 v1(2365,2625.6) ; v1(2485.83,2401.01) 2492,2394.84 2492,2375.02 2559,2308.02 2559,2201.04 2669.65,2090.38 2669.65,2049.29 2819.65,1899.29 2819.65,1519.65 2781,1481 2781,1480.82 2780.8,1480.62 2780.8,1298.72 2844,1235.52 2844,959.71 2803.68,919.39 2803.68,893.26 v1(2816.47,880.48) ; R346.1@3970,310.72 3981.1,321.82 v1(3981.1,336.42)
  BOTTOM w5: v1(2365,2625.6) 2490.83,2499.78 2490.83,2406.01 v1(2485.83,2401.01) ; v1(2816.47,880.48) 2827.94,869 2995.77,869 3004.88,869 3029.89,844 3082.74,844 3303.5,623.25 3308.58,623.25 3386.33,545.5 3386.33,475.67 3461,401 3565,401 3579.3,415.3 3815.45,415.3 3854.4,376.35 3946.5,376.35 3981.1,341.75 v1(3981.1,336.42)
SARADC1_IN5: C277.2 M1.67 R345.1 | length 3778.7
  TOP w5: M1.67@2282.09,2463.78 2282.09,2477.09 2349,2544 2349,2576 2305,2620 2305,2637.28 C277.2@2320,2652.28 2320,2631.67 v1(2326.67,2625) ; v1(2466.11,2377.61) 2470.38,2377.61 2546,2302 2546,2195.65 2656.65,2085 2656.65,2043.91 2806.65,1893.91 2806.65,1525.65 2769.8,1488.8 2769.8,1291.33 2775.61,1285.52 2833,1228.14 2833,967.1 2790.74,924.84 v1(2790.74,870.32) ; R345.1@3930,310.72 3953.44,334.16 v1(3953.44,336.42)
  BOTTOM w5: v1(2326.67,2625) 2354.67,2597 2368,2597 2467.5,2497.5 2467.5,2431.5 2462.5,2426.5 2462.5,2381.22 v1(2466.11,2377.61) ; v1(2790.74,870.32) 2803.07,858 3000.33,858 3018.89,839.44 3025.33,833 3078.19,833 3298.94,612.25 3301.18,612.25 3303.43,610 3311.77,601.66 3366.33,547.1 3366.33,470.67 3452,385 3573,385 3590.3,402.3 3807.24,402.3 3853.19,356.35 3938.21,356.35 3953.44,341.12 v1(3953.44,336.42)
SARADC1_IN6: M1.68
SARADC1_IN7: M1.69
SD_CD: J6.9 R28.2 | length 110
  TOP w5: R28.2@4440,2867.72 4440,2922 4441.46,2923.46 J6.9@4441.46,2977.13
SD_CLK: C279.2 J6.5 R25.2 | length 1504.9
  TOP w5: R25.2@3060,2692.72 C279.2@3100,2692.72 3100,2701 3147.61,2748.61 3185.47,2748.61 3193.62,2756.77 v1(3203.51,2756.77) ; J6.5@4268.23,2977.13 v1(4268.23,3050)
  BOTTOM w5: v1(3203.51,2756.77) 3210.49,2756.77 3229.39,2775.66 3229.39,2782.73 3220.59,2791.52 3220.59,2798.59 3227.67,2805.67 3234.74,2805.67 3243.53,2796.88 3250.6,2796.88 3257.67,2803.95 3257.67,2811.02 3247.24,2821.45 3247.24,2828.52 3254.31,2835.59 3261.38,2835.59 3271.82,2825.16 3278.89,2825.16 3292.48,2838.76 3725.1,2838.76 3877.25,2990.91 4155.91,2990.91 4215,3050 v1(4268.23,3050)
SDMMC0_CLK: M1.51 R25.1 | length 287
  TOP w5: M1.51@2912.01,2463.78 2912.01,2497.01 2965,2550 3020,2550 3060,2590 R25.1@3060,2657.28
SDMMC0_CMD: J6.3 M1.52 | length 1871.7
  TOP w5: M1.52@2872.64,2463.78 2872.64,2494.36 2861,2506 2834.6,2506 2768.55,2572.05 2768.55,2607.86 2809.02,2648.33 2951.33,2648.33 3018,2715 3087.91,2715 3144.85,2771.94 v1(3169.44,2771.94) ; J6.3@4181.61,2977.13 v1(4181.61,3050)
  BOTTOM w5: v1(3169.44,2771.94) 3256.26,2858.76 3723.88,2858.76 3871.04,3005.91 4137.52,3005.91 v1(4181.61,3050)
SDMMC0_D0: J6.7 M1.50 | length 1856.1
  TOP w5: M1.50@2951.38,2463.78 2951.38,2501.38 2980,2530 3028.28,2530 3073.28,2575 3093.32,2575 3099.99,2581.68 3099.99,2588.75 3085.91,2602.83 3085.91,2609.91 3092.98,2616.98 3100.05,2616.98 3114.14,2602.89 3121.21,2602.89 3144,2625.68 3144,2659 3131,2672 3131,2691 3138.51,2698.51 v1(3164.36,2698.51) ; J6.7@4354.84,2977.13 v1(4354.84,3050)
  BOTTOM w5: v1(3164.36,2698.51) 3178.39,2712.54 3204.82,2712.54 3226.17,2733.89 3226.17,2751.23 3293.7,2818.76 3726.31,2818.76 3878.47,2970.91 4164.2,2970.91 4218.5,3025.21 4330.05,3025.21 v1(4354.84,3050)
SDMMC0_D1: J6.8 M1.49 | length 1882.4
  TOP w5: M1.49@2990.75,2463.78 2990.75,2500.75 3010,2520 3032.43,2520 3077.43,2565 3102,2565 3113,2576 3123.84,2576 3139.38,2560.45 3147.45,2560.45 3154.52,2567.53 3154.52,2573.6 3136.1,2592.02 3136.1,2599.09 3143.17,2606.17 3150.24,2606.17 3165.67,2590.74 3173.74,2590.74 3180.81,2597.81 3180.81,2603.88 3164.38,2620.31 3164.38,2627.38 v1(3164.39,2670.47) ; v1(4381.49,3050) 4398.15,3033.34 J6.8@4398.15,2977.13
  BOTTOM w5: v1(3164.39,2670.47) 3164.39,2672.62 3189.56,2697.79 3204.21,2697.79 3236.17,2729.75 3236.17,2747.09 3297.84,2808.76 3730.45,2808.76 3882.61,2960.91 4168.34,2960.91 4222.64,3015.21 4346.7,3015.21 v1(4381.49,3050)
SDMMC0_D2: J6.1 M1.54 | length 1851.7
  TOP w5: M1.54@2793.9,2463.78 2793.9,2518.42 2748.55,2563.76 2748.55,2616.14 2800.73,2668.33 2932.76,2668.33 3008.93,2744.5 3070.5,2744.5 3130.07,2804.07 v1(3130.07,2808.99) ; J6.1@4095,2977.13 v1(4095,3050)
  BOTTOM w5: v1(3130.07,2808.99) 3174.99,2808.99 3244.76,2878.76 3714.12,2878.76 3861.28,3025.91 3938.02,3025.91 3980.61,3068.5 4040.02,3068.5 4045.02,3063.5 4045.02,3036 4050.02,3031 4060.02,3031 4065.02,3036 4065.02,3063.5 4070.02,3068.5 4076.5,3068.5 v1(4095,3050)
SDMMC0_D3: J6.2 M1.53 | length 1910.1
  TOP w5: M1.53@2833.27,2463.78 2833.27,2493.19 2758.55,2567.91 2758.55,2612 2804.88,2658.33 2936.9,2658.33 3011.57,2733 3091.77,2733 v1(3149.04,2790.27) ; J6.2@4138.31,2977.13 v1(4138.31,3050)
  BOTTOM w5: v1(3149.04,2790.27) 3170.41,2790.27 3248.9,2868.76 3718.88,2868.76 3866.04,3015.91 3963.36,3015.91 3968.36,3020.91 3968.36,3038 3973.36,3043 3983.36,3043 3988.36,3038 3988.36,3020.91 3993.36,3015.91 4003.36,3015.91 4008.36,3020.91 4008.36,3044 4013.36,3049 4023.36,3049 4028.36,3044 4028.36,3020.91 4033.36,3015.91 4104.23,3015.91 v1(4138.31,3050)
SDMMC0_DET_L: M1.171 R28.1 R431.2 | length 3489.2
  TOP w5: M1.171@3148.23,707.87 3148.23,734.27 3124.5,758 3056,758 3041.65,772.35 3030.41,772.35 3027.75,775 3000,775 2960,815 2960,860 3031,931 3131,931 3150,950 3150,1015 3192,1057 3192,1302 3201,1311 3201,1934 v1(3195,1940) ; v1(3461,2319) 3454,2326 3454,2351 3523,2420 3675,2420 3695,2440 3740,2440 3785,2485 4379,2485 4420,2526 4420,2755 4440,2775 R28.1@4440,2832.28 R431.2@4400,2832.28
  BOTTOM w5: v1(3195,1940) 3195,1966 3294,2065 3310,2065 3365,2120 3365,2272 3412,2319 v1(3461,2319)
SDMMC1_CLK: M1.43 R227.1 | length 3323
  TOP w5: v1(2935,1419.05) 2935,1459.44 2951.65,1476.1 2951.65,1923.16 3056.64,2028.14 3056.64,2083.36 3050,2090 3050,2348.6 3090.64,2389.24 3117.81,2389.24 3128.57,2400 3200,2400 3212.6,2412.6 M1.43@3238.78,2412.6 ; R227.1@4685,1262.72 v1(4711.68,1262.72)
  BOTTOM w5: v1(2935,1419.05) 2935.71,1418.35 2962.59,1418.35 2981.43,1437.18 3236.81,1437.18 3295.52,1378.47 3346.49,1327.5 3368.17,1327.5 3705.67,990 3729.23,990 3747.83,971.4 4218.32,971.4 4328.26,1081.34 4397.34,1081.34 4525.33,1209.33 4595.33,1209.33 4648.72,1262.72 v1(4711.68,1262.72)
SDMMC1_CMD: M1.44 U18.16 | length 3438.5
  TOP w5: v1(2921.67,1367.4) 2911.67,1377.39 2911.67,1457.33 2936.65,1482.31 2936.65,1936.44 3019.98,2019.77 3019.98,2346.87 3082.35,2409.24 3109.53,2409.24 3120.29,2420 3174,2420 3187.6,2433.6 M1.44@3187.6,2463.78 ; U18.16@4680.43,1149.41 v1(4680.43,1190)
  BOTTOM w5: v1(2921.67,1367.4) 2926.25,1362.82 3261.68,1362.82 3336.99,1287.5 3347.89,1287.5 3703.99,931.4 4303.97,931.4 4480.51,1107.94 4598.37,1107.94 4601.34,1110.91 4647.91,1110.91 4654.98,1117.98 4654.98,1125.05 4638.77,1141.27 4638.77,1148.34 4645.84,1155.41 4652.91,1155.41 4667.12,1141.19 4674.19,1141.19 4681.27,1148.27 4681.27,1155.34 4667.05,1169.55 4667.05,1176.62 v1(4680.43,1190)
SDMMC1_D0: M1.48 U18.18 | length 3404.6
  TOP w5: v1(2868.13,1397) 2849.8,1415.33 2849.8,1452.03 2896.65,1498.89 2896.65,1953.02 2979.98,2036.34 2979.98,2363.44 3030.12,2413.57 M1.48@3030.12,2463.78 ; U18.18@4609.57,1149.41 v1(4609.57,1186)
  BOTTOM w5: v1(2868.13,1397) 2879.4,1385.73 2932.84,1385.73 2945.76,1372.82 3265.82,1372.82 3341.14,1297.5 3353.89,1297.5 3709.99,941.4 4299.83,941.4 4476.37,1117.94 4594.23,1117.94 4599.23,1122.94 4599.23,1132.94 4594.23,1137.94 4516.37,1137.94 4511.37,1142.94 4511.37,1152.94 4516.37,1157.94 4581.51,1157.94 v1(4609.57,1186)
SDMMC1_D1: M1.47 U18.19 | length 3443.3
  TOP w5: v1(2868.13,1426.56) 2874.16,1432.59 2874.16,1462.24 2906.65,1494.74 2906.65,1948.87 2989.98,2032.2 2989.98,2359.3 3069.49,2438.8 M1.47@3069.49,2463.78 ; U18.19@4574.13,1149.41 v1(4574.13,1186)
  BOTTOM w5: v1(2868.13,1426.56) 2898.97,1395.73 2936.99,1395.73 2949.9,1382.82 2962.39,1382.82 2967.39,1387.82 2967.39,1400 2972.39,1405 2982.39,1405 2987.39,1400 2987.39,1387.82 2992.39,1382.82 3228.3,1382.82 3233.3,1387.82 3233.3,1399.48 3238.3,1404.48 3248.3,1404.48 3253.3,1399.48 3253.3,1387.82 3258.3,1382.82 3269.96,1382.82 3345.28,1307.5 3359.89,1307.5 3715.99,951.4 4295.68,951.4 4302.4,958.12 4302.4,965.19 4276.83,990.76 4276.83,997.83 4283.9,1004.9 4290.98,1004.9 4316.55,979.33 4323.62,979.33 4330.69,986.4 4330.69,993.48 4307.12,1017.05 4307.12,1024.12 4314,1031 4321.45,1031 4344.83,1007.62 4351.9,1007.62 4358.98,1014.69 4358.98,1021.76 4338.41,1042.33 4338.41,1049.4 4345.48,1056.48 4352.55,1056.48 4373.12,1035.91 4380.19,1035.91 4514.96,1170.67 4558.8,1170.67 v1(4574.13,1186)
SDMMC1_D2: M1.46 U18.14 | length 3453.2
  TOP w5: v1(2871.15,1350.38) 2878.12,1357.34 2878.12,1381.07 2886.45,1389.41 2886.45,1460.4 2916.65,1490.6 2916.65,1944.73 2999.98,2028.06 2999.98,2355.15 3074.07,2429.24 3101.24,2429.24 3108.86,2436.86 M1.46@3108.86,2463.78 ; v1(4744,1189) 4751.3,1181.7 U18.14@4751.3,1149.41
  BOTTOM w5: v1(2871.15,1350.38) 2882.46,1339.07 3257.14,1339.07 3328.71,1267.5 3339.6,1267.5 3695.7,911.4 4312.26,911.4 4488.8,1087.94 4665.38,1087.94 4744,1166.56 v1(4744,1189)
SDMMC1_D3: M1.45 U18.15 | length 3413.6
  TOP w5: v1(2896.45,1358.76) 2896.45,1456.26 2926.65,1486.46 2926.65,1940.59 3009.98,2023.91 3009.98,2351.01 3078.21,2419.24 3105.38,2419.24 3116.14,2430 3140,2430 3148.23,2438.23 M1.45@3148.23,2463.78 ; U18.15@4715.87,1149.41 v1(4715.87,1190)
  BOTTOM w5: v1(2896.45,1358.76) 2906.14,1349.07 3261.28,1349.07 3332.85,1277.5 3343.74,1277.5 3699.84,921.4 4308.11,921.4 4484.65,1097.94 4661.24,1097.94 4715.87,1152.57 v1(4715.87,1190)
SENSER_SCL: R343.2 U20.6 | length 51.9
  TOP w5: U20.6@2625.71,412.21 2659.49,412.21 R343.2@2672.28,425
SENSER_SDA: R344.2 U20.5 | length 48
  TOP w5: U20.5@2625.71,386.62 2668.9,386.62 R344.2@2672.28,390
SIM_CLK: C62.2 J11.C3 R55.2 U8.6 | length 602.3
  TOP w5: v1(4480.01,2191.9) 4480.01,2134.97 4509.47,2105.5 4578.22,2105.5 R55.2@4600,2127.28
  BOTTOM w5: J11.C3@4440,2424.87 4440,2368.71 C62.2@4410.01,2338.72 4435,2313.72 4435,2236.91 v1(4480.01,2191.9) 4498.11,2210 4555,2210 4580,2185 U8.6@4591.89,2185
SIM_DATA: C63.2 J11.C7 R53.1 R54.2 U8.3 | length 1887.1
  TOP w5: v1(4440,3280) 4440,3172.5 4534.5,3078 4534.5,2960.18 4478.75,2904.43 4478.75,2573.72 v1(4527.47,2525) ; R54.2@4640,2127.28 4680,2127.28 R53.1@4682.28,2125 4682.28,2092.72 v1(4683,2092)
  BOTTOM w5: v1(4440,3280) J11.C7@4440,3337.13 ; v1(4527.47,2525) 4687.47,2365 4832.73,2365 C63.2@4875.01,2322.72 4900,2297.73 4900,2209 4876,2185 ; v1(4683,2092) 4705.5,2114.5 4873.5,2114.5 4885,2126 4885,2176 4876,2185 ; U8.3@4828.11,2185 4876,2185
SIM_RST: C61.2 J11.C2 R56.2 R440.1 U8.7 | length 696.8
  TOP w5: v1(4481.68,2219.68) 4501.65,2199.71 4501.65,2145.63 R440.1@4520,2127.28 R56.2@4560,2127.28
  BOTTOM w5: J11.C2@4340,2424.87 4340,2433 4380,2473 4472,2473 4481.68,2463.32 4481.68,2359.4 C61.2@4460.01,2337.72 4481.68,2316.04 v1(4481.68,2219.68) 4497.01,2235 U8.7@4591.89,2235
SNSN: M1.178 TP1.1 | length 93.1
  TOP w10: v1(3086,1648) 3086,1610.65 M1.178@3096.65,1600
  BOTTOM w10: TP1.1@3065,1680 3065,1669 v1(3086,1648)
SNSP: M1.177 TP2.1 | length 89.1
  TOP w10: v1(3091.65,1402.68) 3096.65,1407.68 M1.177@3096.65,1450
  BOTTOM w10: TP2.1@3055,1410 3062.32,1402.68 v1(3091.65,1402.68)
SPI0_CLK_M0: M1.160 R363.2 | length 2628.2
  TOP w5: v1(2710.51,1021.46) 2676,986.95 2676,809 2715.16,769.84 M1.160@2715.16,707.87 ; v1(4593,430) 4613.33,409.66 4613.33,364.33 4604.84,355.84 R363.2@4604.84,339.69
  BOTTOM w5: v1(2710.51,1021.46) 2719.05,1030 2750,1030 2775.26,1055.26 2818.69,1055.26 2850.5,1087.07 3094.57,1087.07 3275.93,905.72 3308.08,905.72 3400.22,813.57 3417.39,813.57 3599.29,631.67 4022.12,631.67 4054.45,599.35 4307.23,599.35 4406.91,499.67 4511.54,499.67 4581.22,430 v1(4593,430)
SPI0_CLK_M0/PWM0_M0: J44.4 R363.7 | length 276.3
  TOP w5: R363.7@4604.84,300.31 4604.84,273.09 4683,194.93 4683,137 J44.4@4740,80
SPI0_CSN0_M0: M1.159 R363.1 | length 2693.3
  TOP w5: M1.159@2675.79,707.87 2675.79,740.79 2690,755 2690,770 2665,795 2665,934.79 2665,1005 2712.96,1052.96 v1(2747.04,1052.96) ; R363.1@4626.5,339.69 4626.5,357.14 4628.33,358.98 4628.33,414.71 4626.82,416.22 v1(4626.82,429.16)
  BOTTOM w5: v1(2747.04,1052.96) 2764.34,1070.26 2812.48,1070.26 2844.29,1102.07 3100.79,1102.07 3280.14,922.72 3312.29,922.72 3406.43,828.57 3423.61,828.57 3605.51,646.67 4028.34,646.67 4060.66,614.35 4313.44,614.35 4413.12,514.67 4517.76,514.67 4542.86,489.57 4580.56,489.57 4600.52,469.6 4600.52,455.46 v1(4626.82,429.16)
SPI0_CSN0_M0/PWM5_M0: J44.2 R363.8 | length 346.2
  TOP w5: R363.8@4626.5,300.31 4626.5,265.58 4693,199.08 4693,163 4730,126 4794,126 J44.2@4840,80
SPI0_MISO_M0: M1.162 R363.4 | length 2542.9
  TOP w5: v1(2714.98,978.8) 2697.46,961.28 2697.46,824.25 2793.9,727.81 M1.162@2793.9,707.87 ; R363.4@4563.5,339.69 v1(4563.5,394.44)
  BOTTOM w5: v1(2714.98,978.8) 2727.51,991.33 2746.33,991.33 2785.26,1030.26 2829.05,1030.26 2860.86,1062.07 3084.21,1062.07 3265.57,880.72 3295.51,880.72 3387.65,788.57 3407.03,788.57 3588.93,606.67 4011.77,606.67 4044.09,574.35 4296.87,574.35 4396.55,474.67 4501.18,474.67 4556.58,419.28 4556.58,401.37 v1(4563.5,394.44)
SPI0_MISO_M0/PWM2_M0: J44.8 R363.5 | length 244.5
  TOP w5: J44.8@4540,80 4581,121 4581,216 4563.5,233.5 R363.5@4563.5,300.31
SPI0_MOSI_M0: M1.161 R363.3 | length 2579.6
  TOP w5: v1(2737.2,1010) 2725.33,998.13 2708.39,998.13 2687.46,977.2 2687.46,817.54 2754.53,750.47 M1.161@2754.53,707.87 ; R363.3@4585.16,339.69 4585.16,395.16 v1(4590,400)
  BOTTOM w5: v1(2737.2,1010) 2750,1010 2780.26,1040.26 2824.91,1040.26 2856.72,1072.07 3088.36,1072.07 3269.71,890.72 3299.65,890.72 3391.79,798.57 3411.18,798.57 3593.08,616.67 4015.91,616.67 4048.23,584.35 4301.02,584.35 4400.69,484.67 4505.33,484.67 v1(4590,400)
SPI0_MOSI_M0/PWM1_M0: J44.6 R363.6 | length 243
  TOP w5: R363.6@4585.16,300.31 4585.16,230.84 4594,222 4594,126 J44.6@4640,80
SPK_CTL_L: Q5.3 U25.5 U25.12 | length 522.8
  TOP w5: U25.12@3585,650 U25.5@3825,650 3901,650 3914,663 3996,663 4048.93,715.93 4048.93,725 4043.93,730 Q5.3@4028.5,730
SPK_EN_H_GPIO4_B6_D: M1.114 R454.1 R1201.1 | length 3807.3
  TOP w5: v1(1408.32,1302) 1408.32,1318.32 1439.61,1349.61 M1.114@1482.87,1349.61 ; v1(3771.97,367.97) 3771.97,382.97 3789,400 3878.04,400 3898.33,420.3 4120.06,420.3 4171.35,471.58 4171.35,681.32 4192,701.97 4192,734.72 R454.1@4171,755.72 R1201.1@4171,795.28
  BOTTOM w5: v1(1408.32,1302) 1413.65,1296.68 1442.7,1296.68 1636.91,1102.47 1636.91,1026.95 1727.53,936.33 2508.39,936.33 2589.72,855 2699.14,855 2793.14,761 2955,761 2975,781 2975,795 2993,813 3068.86,813 3291.86,590 3295.14,590 3346.33,538.82 3346.33,452.67 3448.67,350.33 3669.8,350.33 3687.8,368.33 3696.08,368.33 3771.62,368.33 v1(3771.97,367.97)
SPKN_OUT: M1.175 TP5.1 | length 528.2
  TOP w20: v1(2870,805) 2870,861 2985,976 2985,1045 3035,1095 3085,1095 3096.65,1106.65 M1.175@3096.65,1150
  BOTTOM w20: TP5.1@2810,805 v1(2870,805)
SPKP_OUT: M1.174 TP4.1 | length 444.7
  TOP w20: v1(2909.84,805) 2909.84,855.84 3025,971 3025,1030 3055,1060 3080.77,1060 3096.65,1044.12 M1.174@3096.65,1000
  BOTTOM w20: v1(2909.84,805) 2914.84,800 TP4.1@2945,800
SYS_LED_H: R21.1 R415.2 R1173.1 | length 139.4
  TOP w10: R1173.1@2925,3267.72 2985,3327.72 R21.1@2985,3342.28 R415.2@3025,3342.28
TN: R206.3 U17.4 | length 90.6
  BOTTOM w4: U17.4@1335.15,2354.5 1335.15,2369.85 1330.3,2374.7 1330.3,2387.32 1329.33,2388.29 1329.33,2434.49 R206.3@1335.16,2440.32
TP: R206.4 U17.3 | length 90.6
  BOTTOM w4: R206.4@1313.5,2440.32 1319.33,2434.49 1319.33,2384.15 1320.3,2383.18 1320.3,2374.3 1315.45,2369.45 U17.3@1315.45,2354.5
TP_INT: J13.3 R449.1 U59.4 | length 871.9
  TOP w5: J13.3@262.01,1740.16 299.16,1740.16 339,1780 v1(400,1780) ; R449.1@442.72,1205 467.72,1230 v1(470,1230) 470,1241.2 488.05,1259.25 U59.4@506.54,1259.25
  BOTTOM w5: v1(400,1780) 381.67,1761.67 381.67,1737.88 407,1712.55 407,1572.71 506.67,1473.04 506.67,1266.67 v1(470,1230)
TP_INT_L_GPIO0_B6_D: M1.156 U59.8 | length 2482.3
  TOP w5: U59.8@573.47,1259.25 595.75,1259.25 615,1240 v1(615,1173.67) ; v1(2544.93,750) 2557.68,737.25 M1.156@2557.68,707.87
  BOTTOM w5: v1(615,1173.67) 643.33,1145.34 684.81,1145.34 732.8,1193.33 933.39,1193.33 983.57,1143.14 1152.58,1143.14 1253.11,1243.67 1424.99,1243.67 1586.91,1081.76 1586.91,1006.23 1706.82,886.33 2487.67,886.33 2540.69,833.31 2540.69,754.24 v1(2544.93,750)
TP_RST: J13.2 U59.5 | length 842.8
  TOP w5: J13.2@262.01,1720.47 306,1720.47 346,1760.47 389.53,1760.47 v1(400,1750) ; v1(470,1200) 488.33,1218.33 488.33,1238.33 493.5,1243.5 U59.5@506.54,1243.5
  BOTTOM w5: v1(400,1750) 417,1733 417,1576.85 516.67,1477.18 516.67,1246.67 v1(470,1200)
TP_RST_L_GPIO0_B5_D: M1.155 U59.7 | length 2465.5
  TOP w5: U59.7@573.47,1243.5 591.5,1243.5 600.03,1234.97 600.03,1185.35 v1(588.35,1173.67) ; M1.155@2518.31,707.87 v1(2518.31,751.26)
  BOTTOM w5: v1(588.35,1173.67) 626.67,1135.34 688.95,1135.34 736.94,1183.33 929.24,1183.33 979.43,1133.14 1156.73,1133.14 1246.73,1223.15 1366.38,1223.15 1386.05,1203.48 1451.04,1203.48 1576.91,1077.61 1576.91,1002.09 1702.67,876.33 2483.53,876.33 2529.82,830.04 2529.82,783.49 2518.31,771.97 v1(2518.31,751.26)
TP_SCL: J13.4 R422.1 U59.3 | length 855
  TOP w5: J13.4@262.01,1759.84 295,1759.84 335,1799.84 389.84,1799.84 v1(400,1810) ; R422.1@442.72,1245 463.64,1265.92 v1(468.81,1265.92) 477.88,1275 U59.3@506.54,1275
  BOTTOM w5: v1(400,1810) 371.67,1781.67 371.67,1733.74 397,1708.41 397,1568.56 496.67,1468.89 496.67,1292.39 470.21,1265.92 v1(468.81,1265.92)
TP_SDA: J13.5 R421.1 U59.2 | length 852.4
  TOP w5: J13.5@262.01,1779.53 290,1779.53 330,1819.53 379.53,1819.53 v1(400,1840) ; R421.1@442.72,1285 463.36,1285 v1(470.86,1292.5) 482.5,1292.5 484.25,1290.75 U59.2@506.54,1290.75
  BOTTOM w5: v1(400,1840) 361.67,1801.67 361.67,1729.59 387,1704.26 387,1564.42 486.67,1464.75 486.67,1308.31 v1(470.86,1292.5)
